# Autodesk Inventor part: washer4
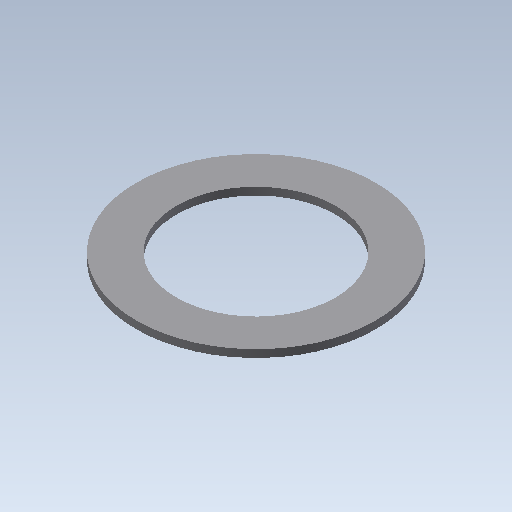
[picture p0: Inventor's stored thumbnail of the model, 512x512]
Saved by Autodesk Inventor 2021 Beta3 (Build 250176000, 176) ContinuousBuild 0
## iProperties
Created: 2012-08
Part Number: washer4
Material: Generic
Document SubType Name: Modeling
Designer: John
Density: 1 g/cm^3
Appearance: Default
Author: John
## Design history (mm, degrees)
sketch "Sketch1"
  geometry: C1 r 6.032 at (0, 0); 1 further point
  constraints: 1 centre point, 1 coincident
  dimensions: "d0" = 12.065 diameter of C1
extrude "Extrusion1" new body sketch "Sketch1" distance "d1" = 0.381; taper "d2" = 0 deg
sketch "Sketch2"
  geometry: C1 r 6.032 at (0, 0) reference; C2 r 4.013 at (0, 0)
  constraints: 1 centre point, 1 coincident
  dimensions: "d3" = 8.0264 diameter of C2
extrude "Extrusion2" cut sketch "Sketch2" extent not by distance; stored distance "d4" = 0.381; taper "d5" = 0 deg
body "Solid1"
